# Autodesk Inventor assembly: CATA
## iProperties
Created: 2002-07
Part Number: CATA
Document SubType Name: Assembly
Designer: Administrator
Control State: 0
Master: False
Checked Out: False
Shininess: 64.0
Length Units: 11269
Angle Units: 11279
Time Units: 11290
Mass Units: 11283
Length Display Precision: 3
Angle Display Precision: 2
Density: 0.0
Volumn: 0.0
Area: 0.0
PropertySet Name: Model Information
Author: Administrator
